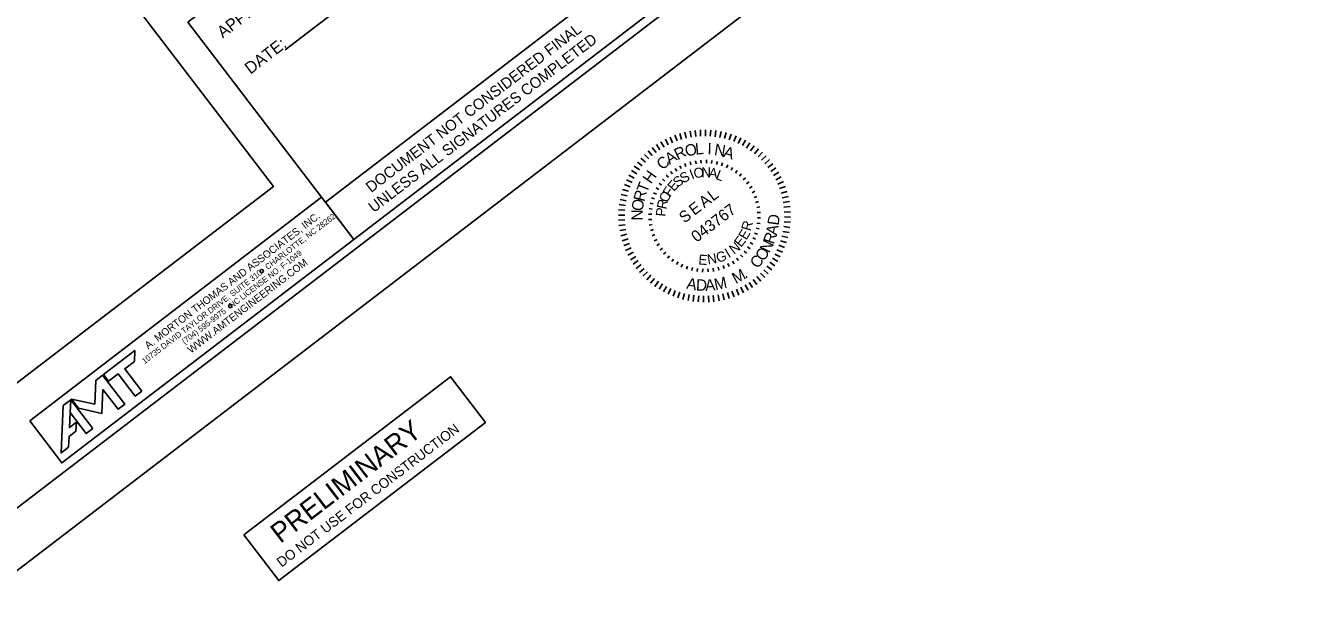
# Model space of a CAD drawing. Extents: x -642 to 2005, y -4412 to 1950.
# Drawn here: x 1361 to 2005, y 564 to 854 of the extents above; entities that cross this region are included whole.
import ezdxf

# ---------------------------------------------------------------- set-up
doc = ezdxf.new("R2010")
doc.units = 0
for name, color, linetype in [('Default', 7, 'Continuous'), ('DEV BORDER CELL', 7, 'Continuous'), ('DEV PRELIMINARY STAMP CELL', 7, 'Continuous'), ('Gray Area Fill Shapes', 7, 'Continuous'), ('Scratch_Level_0', 7, 'Continuous'), ('Sheet Block Title CELL', 7, 'Continuous'), ('Sheet Plot Border Outside CELL', 7, 'Continuous'), ('Sheet Sticker Exception Certification CELL', 7, 'Continuous')]:
    doc.layers.add(name, color=color, linetype=linetype)

msp = doc.modelspace()

# ---------------------------------------------------------------- linework, layer by layer
at = {"layer": 'Default'}
for p, q in [((1688.69, 796.09), (1687.61, 799.04)), ((1690.99, 796.86), (1690.09, 799.86)), ((1693.34, 797.49), (1692.62, 800.54)), ((1695.72, 797.97), (1695.19, 801.05)), ((1698.12, 798.3), (1697.78, 801.42)), ((1700.54, 798.5), (1700.39, 801.63)), ((1702.97, 798.54), (1703.01, 801.67)), ((1705.4, 798.44), (1705.63, 801.57)), ((1707.82, 798.19), (1708.23, 801.3)), ((1710.21, 797.8), (1710.81, 800.87)), ((1712.58, 797.26), (1713.37, 800.29)), ((1714.92, 796.58), (1715.88, 799.56)), ((1717.2, 795.76), (1718.35, 798.68)), ((1678.08, 790.27), (1676.17, 792.76)), ((1680.05, 791.69), (1678.3, 794.29)), ((1682.1, 792.99), (1680.52, 795.69)), ((1684.23, 794.16), (1682.81, 796.95)), ((1686.43, 795.19), (1685.18, 798.06)), ((1719.44, 794.81), (1720.75, 797.65)), ((1721.61, 793.72), (1723.09, 796.47)), ((1723.71, 792.5), (1725.36, 795.16)), ((1725.73, 791.16), (1727.54, 793.71)), ((1727.67, 789.69), (1729.63, 792.14)), ((1672.72, 785.35), (1670.4, 787.45)), ((1674.4, 787.1), (1672.22, 789.34)), ((1676.19, 788.74), (1674.14, 791.11)), ((1695.65, 784.07), (1695.25, 785.59)), ((1698.21, 784.62), (1697.95, 786.16)), ((1700.8, 784.91), (1700.7, 786.47)), ((1703.42, 784.95), (1703.47, 786.51)), ((1706.02, 784.73), (1706.23, 786.28)), ((1708.59, 784.26), (1708.95, 785.78)), ((1729.52, 788.12), (1731.62, 790.44)), ((1731.26, 786.43), (1733.51, 788.62)), ((1732.91, 784.64), (1735.28, 786.69)), ((1668.34, 779.54), (1665.68, 781.19)), ((1669.68, 781.56), (1667.12, 783.37)), ((1671.14, 783.5), (1668.7, 785.46)), ((1686.32, 779.49), (1685.37, 780.73)), ((1688.48, 780.97), (1687.65, 782.3)), ((1690.76, 782.24), (1690.07, 783.65)), ((1693.16, 783.27), (1692.62, 784.74)), ((1711.1, 783.54), (1711.61, 785.02)), ((1713.53, 782.58), (1714.18, 784)), ((1715.86, 781.38), (1716.64, 782.73)), ((1718.05, 779.95), (1718.97, 781.23)), ((1720.1, 778.33), (1721.13, 779.5)), ((1734.44, 782.76), (1736.93, 784.66)), ((1735.86, 780.78), (1738.46, 782.54)), ((1737.15, 778.73), (1739.86, 780.32)), ((1665.08, 773.03), (1662.16, 774.18)), ((1666.03, 775.27), (1663.19, 776.58)), ((1667.12, 777.44), (1664.36, 778.93)), ((1680.88, 773.88), (1679.61, 774.8)), ((1682.51, 775.93), (1681.33, 776.96)), ((1684.33, 777.8), (1683.26, 778.95)), ((1721.97, 776.51), (1723.12, 777.58)), ((1723.66, 774.51), (1724.9, 775.46)), ((1725.14, 772.36), (1726.47, 773.19)), ((1738.32, 776.6), (1741.12, 778.02)), ((1739.36, 774.4), (1742.23, 775.66)), ((1740.27, 772.15), (1743.2, 773.23)), ((1663.04, 766.05), (1659.96, 766.65)), ((1663.57, 768.42), (1660.54, 769.2)), ((1664.26, 770.75), (1661.28, 771.71)), ((1677.3, 766.94), (1675.81, 767.44)), ((1678.26, 769.37), (1676.84, 770.02)), ((1679.46, 771.69), (1678.1, 772.47)), ((1726.41, 770.07), (1727.81, 770.76)), ((1727.44, 767.67), (1728.91, 768.22)), ((1741.03, 769.84), (1744.03, 770.74)), ((1741.66, 767.5), (1744.71, 768.21)), ((1662.4, 761.23), (1659.27, 761.46)), ((1662.64, 763.65), (1659.54, 764.06)), ((1676.1, 761.85), (1674.55, 762.06)), ((1676.58, 764.42), (1675.05, 764.78)), ((1728.24, 765.19), (1729.75, 765.59)), ((1728.79, 762.63), (1730.33, 762.88)), ((1729.08, 760.03), (1730.64, 760.13)), ((1742.14, 765.12), (1745.22, 765.65)), ((1742.47, 762.71), (1745.59, 763.05)), ((1742.66, 760.29), (1745.79, 760.44)), ((1662.3, 758.8), (1659.16, 758.84)), ((1662.34, 756.38), (1659.21, 756.22)), ((1662.53, 753.96), (1659.42, 753.61)), ((1675.89, 759.25), (1674.32, 759.3)), ((1675.92, 756.64), (1674.36, 756.54)), ((1676.22, 754.04), (1674.67, 753.79)), ((1728.9, 754.81), (1730.45, 754.61)), ((1729.12, 757.42), (1730.69, 757.36)), ((1742.61, 755.43), (1745.73, 755.21)), ((1742.71, 757.86), (1745.84, 757.83)), ((1662.87, 751.55), (1659.78, 751.02)), ((1663.35, 749.17), (1660.3, 748.45)), ((1676.76, 751.48), (1675.25, 751.08)), ((1677.56, 748.99), (1676.09, 748.44)), ((1726.74, 747.3), (1728.17, 746.65)), ((1727.71, 749.73), (1729.19, 749.22)), ((1728.43, 752.24), (1729.95, 751.88)), ((1741.43, 748.25), (1744.46, 747.47)), ((1741.96, 750.62), (1745.04, 750.02)), ((1742.36, 753.02), (1745.46, 752.6)), ((1663.98, 746.82), (1660.97, 745.93)), ((1664.74, 744.52), (1661.8, 743.44)), ((1665.64, 742.26), (1662.77, 741.01)), ((1678.6, 746.59), (1677.19, 745.9)), ((1679.86, 744.31), (1678.53, 743.48)), ((1681.35, 742.16), (1680.1, 741.2)), ((1722.5, 740.74), (1723.67, 739.71)), ((1724.12, 742.78), (1725.4, 741.87)), ((1725.54, 744.98), (1726.9, 744.19)), ((1738.97, 741.4), (1741.82, 740.08)), ((1739.93, 743.63), (1742.84, 742.49)), ((1740.75, 745.92), (1743.73, 744.96)), ((1666.68, 740.07), (1663.89, 738.64)), ((1667.85, 737.94), (1665.15, 736.35)), ((1669.15, 735.88), (1666.54, 734.13)), ((1683.03, 740.16), (1681.89, 739.09)), ((1684.91, 738.34), (1683.87, 737.16)), ((1686.95, 736.71), (1686.04, 735.44)), ((1689.15, 735.29), (1688.36, 733.94)), ((1691.47, 734.09), (1690.82, 732.67)), ((1714.24, 734.43), (1714.93, 733.02)), ((1716.53, 735.69), (1717.35, 734.36)), ((1718.68, 737.18), (1719.63, 735.93)), ((1720.68, 738.86), (1721.74, 737.72)), ((1735.32, 735.1), (1737.88, 733.29)), ((1736.66, 737.13), (1739.33, 735.48)), ((1737.89, 739.23), (1740.64, 737.74)), ((1670.56, 733.91), (1668.07, 732.01)), ((1672.09, 732.02), (1669.72, 729.98)), ((1673.74, 730.24), (1671.5, 728.05)), ((1675.49, 728.55), (1673.38, 726.23)), ((1693.9, 733.13), (1693.39, 731.65)), ((1696.41, 732.41), (1696.05, 730.88)), ((1698.98, 731.94), (1698.77, 730.38)), ((1701.59, 731.72), (1701.53, 730.15)), ((1704.2, 731.76), (1704.3, 730.19)), ((1706.8, 732.05), (1707.05, 730.51)), ((1709.35, 732.6), (1709.75, 731.08)), ((1711.84, 733.39), (1712.39, 731.92)), ((1728.81, 727.93), (1730.86, 725.56)), ((1730.6, 729.57), (1732.79, 727.33)), ((1732.28, 731.32), (1734.61, 729.21)), ((1733.86, 733.16), (1736.31, 731.2)), ((1677.33, 726.98), (1675.37, 724.53)), ((1679.27, 725.51), (1677.46, 722.96)), ((1681.3, 724.17), (1679.65, 721.51)), ((1683.4, 722.95), (1681.91, 720.19)), ((1685.57, 721.86), (1684.25, 719.02)), ((1718.57, 721.47), (1719.82, 718.6)), ((1720.77, 722.51), (1722.19, 719.72)), ((1722.9, 723.68), (1724.49, 720.98)), ((1724.95, 724.98), (1726.7, 722.38)), ((1726.93, 726.39), (1728.83, 723.9)), ((1687.8, 720.91), (1686.66, 717.99)), ((1690.09, 720.09), (1689.12, 717.11)), ((1692.42, 719.41), (1691.63, 716.37)), ((1694.79, 718.87), (1694.19, 715.8)), ((1697.19, 718.48), (1696.77, 715.37)), ((1699.6, 718.23), (1699.38, 715.1)), ((1702.03, 718.13), (1701.99, 714.99)), ((1704.46, 718.17), (1704.61, 715.04)), ((1706.88, 718.36), (1707.22, 715.25)), ((1709.29, 718.7), (1709.81, 715.61)), ((1711.66, 719.18), (1712.38, 716.13)), ((1714.01, 719.81), (1714.91, 716.8)), ((1716.32, 720.57), (1717.4, 717.63))]:
    msp.add_line(p, q, dxfattribs=at)
msp.add_lwpolyline([(1362.72, 655.35), (1509.7, 767.74), (1525.88, 746.59), (1378.89, 634.2)], close=True, dxfattribs=at)
at = {"layer": 'DEV BORDER CELL'}
msp.add_line((1491.28, 841.93), (1554.67, 890.39), dxfattribs=at)
for points in [[(1331.69, 1914.53), (140.13, 1003.39), (777.93, 169.29), (1969.49, 1080.44)], [(1442.35, 855.82), (1601.26, 977.33), (1684.78, 868.1), (1525.88, 746.59)]]:
    msp.add_lwpolyline(points, close=True, dxfattribs=at)
at = {"layer": 'DEV PRELIMINARY STAMP CELL'}
msp.add_lwpolyline([(1470.53, 597.93), (1574.61, 677.51), (1592.17, 654.55), (1488.1, 574.97)], close=True, dxfattribs=at)
msp.add_lwpolyline([(1470.53, 597.93), (1574.61, 677.51), (1592.17, 654.55), (1488.1, 574.97)], close=True, dxfattribs=at)
at = {"layer": 'Gray Area Fill Shapes'}
msp.add_lwpolyline([(1470.53, 597.93), (1574.61, 677.51), (1592.17, 654.55), (1488.1, 574.97)], close=True, dxfattribs=at)
at = {"layer": 'Scratch_Level_0'}
msp.add_lwpolyline([(1322.34, 1844.44), (210.22, 994.04), (787.28, 239.38), (1485.42, 773.22), (1413.58, 867.17), (1827.56, 1183.74)], close=True, dxfattribs=at)
at = {"layer": 'Sheet Block Title CELL'}
msp.add_lwpolyline([(1362.72, 655.35), (1509.7, 767.74), (1525.88, 746.59), (1378.89, 634.2)], close=True, dxfattribs=at)
for points in [[(1419.18, 670.3), (1410.62, 681.5), (1415.45, 685.19), (1415.68, 690.65), (1399.87, 678.56), (1402.42, 675.23), (1407.29, 678.95), (1415.85, 667.75), (1419.18, 670.3)], [(1399.09, 658.99), (1399.64, 671.07), (1407.22, 661.15), (1410.56, 663.7), (1399.45, 678.23), (1396.11, 675.69), (1395.49, 663.71), (1383.83, 666.3), (1387.37, 661.67), (1399.09, 658.99)], [(1383.06, 659.51), (1383.41, 665.97), (1379.51, 662.99), (1378.56, 639.23), (1382.33, 642.12), (1382.54, 647.45), (1385.99, 650.09), (1386.27, 654.66), (1382.69, 651.92), (1383.06, 659.51)], [(1394.52, 651.44), (1383.41, 665.97), (1383.06, 659.51), (1391.19, 648.89), (1394.52, 651.44)]]:
    msp.add_lwpolyline(points, dxfattribs=at)
for centre in [(1479.55, 730.6), (1463.72, 713.01)]:
    msp.add_circle(centre, 0.833, dxfattribs=at)
at = {"layer": 'Sheet Plot Border Outside CELL'}
msp.add_lwpolyline([(663.64, 50.42), (2004.54, 1075.77), (1336.37, 1949.58), (-4.54, 924.23)], close=True, dxfattribs=at)
at = {"layer": 'Sheet Sticker Exception Certification CELL'}
for p, q in [((1511.6, 765.26), (1670.51, 886.77)), ((1684.78, 868.1), (1525.88, 746.59)), ((1525.88, 746.59), (1511.6, 765.26))]:
    msp.add_line(p, q, dxfattribs=at)

# ---------------------------------------------------------------- texts
at = {"layer": 'Default'}
for s, height, rotation, p in [('R', 5.74, 26.18947, (1688.96, 786.35)), ('O', 5.74, 12.01101, (1693.29, 788.19)), ('L', 5.74, 4.92178, (1698, 789.18)), ('I', 5.74, 357.83255, (1703.89, 789.43)), ('N', 5.74, 350.74332, (1707.12, 789.11)), ('A', 5.74, 343.65409, (1711.57, 788.11)), ('C', 5.74, 40.36793, (1681.32, 781.17)), ('A', 5.74, 33.2787, (1684.89, 784)), ('H', 5.74, 54.54639, (1675.53, 774.11)), ('S', 5.01, 28.27335, (1691.68, 774.63)), ('I', 5.01, 21.24123, (1696.12, 776.75)), ('O', 5.01, 7.17699, (1697.29, 777.31)), ('N', 5.01, 0.14487, (1700.9, 777.81)), ('A', 5.01, 353.11275, (1704.38, 777.73)), ('L', 5.01, 339.04851, (1707.8, 777.05)), ('T', 5.74, 68.72485, (1673.49, 769.59)), ('F', 5.01, 56.40183, (1685.19, 767.48)), ('E', 5.01, 49.36971, (1687.15, 770.36)), ('S', 5.01, 35.30547, (1688.81, 772.51)), ('O', 5.74, 82.90331, (1671.42, 760.6)), ('R', 5.74, 75.81408, (1672.15, 765.24)), ('R', 5.01, 77.49819, (1683.24, 761.44)), ('O', 5.01, 70.46607, (1684.13, 764.82)), ('A', 5.74, 37.40396, (1702.36, 762.15)), ('L', 5.74, 37.40396, (1706.76, 765.55)), ('N', 5.74, 89.99254, (1671.38, 756.04)), ('P', 5.01, 84.53031, (1682.89, 757.89)), ('S', 5.74, 37.40396, (1692.37, 754.48)), ('E', 5.74, 37.40396, (1697.39, 758.39)), ('043767', 5.744, 37.40396, (1698.54, 744.84)), ('R', 5.01, 73.30121, (1725.63, 750.48)), ('A', 5.74, 78.74556, (1738.88, 748.41)), ('D', 5.74, 81.91407, (1739.78, 753.37)), ('E', 5.01, 52.20485, (1720.92, 742.32)), ('E', 5.01, 59.23696, (1723.54, 745.95)), ('R', 5.74, 71.28464, (1737.3, 743.78)), ('G', 5.01, 17.04424, (1709.18, 734.76)), ('I', 5.01, 31.10848, (1714.66, 737.07)), ('N', 5.01, 38.1406, (1717.31, 738.82)), ('O', 5.74, 56.1141, (1732.32, 735.2)), ('N', 5.74, 63.82372, (1735.14, 739.4)), ('E', 5.01, 355.94788, (1699.31, 733.98)), ('N', 5.01, 10.01212, (1704.28, 733.94)), ('C', 5.74, 48.65317, (1729.08, 731.54)), ('M', 5.74, 12.09465, (1707.99, 721.01)), ('M', 5.74, 28.4465, (1718.24, 724.03)), ('.', 5.74, 36.90222, (1723.09, 726.7)), ('A', 5.74, 350.06424, (1693.1, 721.8)), ('D', 5.74, 356.9241, (1698.07, 720.9)), ('A', 5.74, 4.38502, (1702.95, 720.62))]:
    msp.add_text(s, height=height, rotation=rotation, dxfattribs=at).set_placement(p)
at = {"layer": 'DEV BORDER CELL'}
for s, p in [('APPROVED:  ', (1459.96, 847.56)), ('DATE:  ', (1473.87, 829.37))]:
    msp.add_text(s, height=6, rotation=37.40396, dxfattribs=at).set_placement(p)
at = {"layer": 'DEV PRELIMINARY STAMP CELL'}
for s, height, p in [(' PRELIMINARY', 9.9999, (1485.95, 591.15)), ('DO NOT USE FOR CONSTRUCTION', 5.0001, (1489.52, 581.45))]:
    msp.add_text(s, height=height, rotation=37.40396, dxfattribs=at).set_placement(p)
at = {"layer": 'Sheet Block Title CELL'}
for s, height, p in [('10735 DAVID TAYLOR DRIVE, SUITE 310   CHARLOTTE, NC 28262', 2.9167, (1420.61, 683.78)), ('A. MORTON THOMAS AND ASSOCIATES, INC.', 3.75, (1422.4, 691.18)), ('(704) 595-9975   NC LICENSE NO. F-1049', 2.9167, (1440.74, 693.66)), ('WWW.AMTENGINEERING.COM', 3.75, (1443.98, 689.06))]:
    msp.add_text(s, height=height, rotation=37.40348, dxfattribs=at).set_placement(p)
at = {"layer": 'Sheet Sticker Exception Certification CELL'}
for s, p in [('DOCUMENT NOT CONSIDERED FINAL', (1534.62, 769.84)), ('UNLESS ALL SIGNATURES COMPLETED', (1535.94, 759.77))]:
    msp.add_text(s, height=5.5, rotation=37.40396, dxfattribs=at).set_placement(p)

doc.saveas('drawing.dxf')
